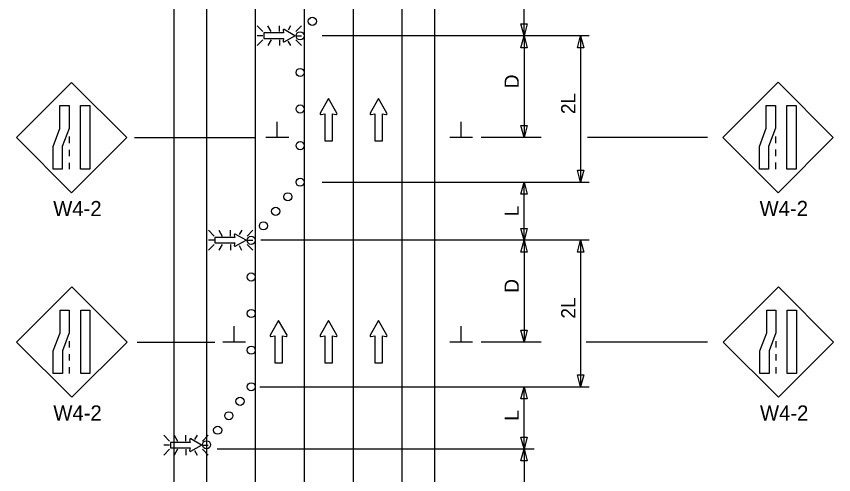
# Model space of a CAD drawing. Extents: x 16364 to 18480, y 5564 to 6927.
# Drawn here: x 16764.6 to 17166.1, y 6445.6 to 6671 of the extents above; entities that cross this region are included whole.
import ezdxf

# ---------------------------------------------------------------- set-up
doc = ezdxf.new("R2010")
doc.units = 0
for name, color, linetype in [('ALI_LEGAL_EX', 7, 'Continuous'), ('MT_SCRATCH_LEVEL_E', 7, 'Continuous'), ('PAVT_EDGE_EX', 7, 'Continuous'), ('TRAFFIC_SIGNS_PR', 7, 'Continuous'), ('TYPICAL_TEXT_DIMEN_PR', 7, 'Continuous')]:
    doc.layers.add(name, color=color, linetype=linetype)

msp = doc.modelspace()

# ---------------------------------------------------------------- linework, layer by layer
at = {"layer": 'ALI_LEGAL_EX'}
for p, q in [((16881.97, 6876.43), (16881.97, 5996.39)), ((16905.97, 6876.43), (16905.97, 5996.39)), ((16929.97, 6876.43), (16929.97, 5996.39))]:
    msp.add_line(p, q, dxfattribs=at)
for points in [[(16881.97, 6596.46), (16881.97, 6571.46)], [(16929.97, 6596.46), (16929.97, 6571.46)], [(16905.97, 6496.46), (16905.97, 6471.46)], [(16929.97, 6496.46), (16929.97, 6471.46)]]:
    msp.add_lwpolyline(points, dxfattribs=at)
at = {"layer": 'MT_SCRATCH_LEVEL_E'}
for p, q in [((16917.93, 6630.62), (16913.82, 6623.38)), ((16922.08, 6623.38), (16917.93, 6630.62)), ((16942.49, 6630.62), (16938.38, 6623.38)), ((16946.64, 6623.38), (16942.49, 6630.62)), ((16914.31, 6622.7), (16916.08, 6623.02)), ((16916.08, 6623.02), (16916.08, 6609.76)), ((16919.82, 6609.76), (16919.82, 6623.02)), ((16919.82, 6623.02), (16921.6, 6622.7)), ((16938.86, 6622.7), (16940.64, 6623.02)), ((16940.64, 6623.02), (16940.64, 6609.76)), ((16944.38, 6609.76), (16944.38, 6623.02)), ((16944.38, 6623.02), (16946.16, 6622.7)), ((16916.08, 6609.76), (16919.82, 6609.76)), ((16940.64, 6609.76), (16944.38, 6609.76)), ((16893.4, 6521.46), (16889.29, 6514.22)), ((16897.55, 6514.22), (16893.4, 6521.46)), ((16917.93, 6521.46), (16913.82, 6514.22)), ((16922.08, 6514.22), (16917.93, 6521.46)), ((16942.49, 6521.46), (16938.38, 6514.22)), ((16946.64, 6514.22), (16942.49, 6521.46)), ((16889.78, 6513.53), (16891.55, 6513.85)), ((16891.55, 6513.85), (16891.55, 6500.59)), ((16895.3, 6500.59), (16895.3, 6513.85)), ((16895.3, 6513.85), (16897.07, 6513.53)), ((16914.31, 6513.53), (16916.08, 6513.85)), ((16916.08, 6513.85), (16916.08, 6500.59)), ((16919.82, 6500.59), (16919.82, 6513.85)), ((16919.82, 6513.85), (16921.6, 6513.53)), ((16938.86, 6513.53), (16940.64, 6513.85)), ((16940.64, 6513.85), (16940.64, 6500.59)), ((16944.38, 6500.59), (16944.38, 6513.85)), ((16944.38, 6513.85), (16946.16, 6513.53)), ((16891.55, 6500.59), (16895.3, 6500.59)), ((16916.08, 6500.59), (16919.82, 6500.59)), ((16940.64, 6500.59), (16944.38, 6500.59))]:
    msp.add_line(p, q, dxfattribs=at)
for centre, start, end in [((16914.23, 6623.16), 150.4248, 279.9638), ((16921.67, 6623.16), 260.0362, 29.7731), ((16938.79, 6623.16), 150.4248, 279.9638), ((16946.23, 6623.16), 260.0362, 29.7731), ((16889.7, 6513.99), 150.4248, 279.9638), ((16897.14, 6513.99), 260.0362, 29.7731), ((16914.23, 6513.99), 150.4248, 279.9638), ((16921.67, 6513.99), 260.0362, 29.7731), ((16938.79, 6513.99), 150.4248, 279.9638), ((16946.23, 6513.99), 260.0362, 29.7731)]:
    msp.add_arc(centre, 0.463, start, end, dxfattribs=at)
at = {"layer": 'PAVT_EDGE_EX'}
for p, q in [((16841.97, 6926.69), (16841.97, 5953.59)), ((16857.97, 6926.69), (16857.97, 5953.59)), ((16953.97, 6926.69), (16953.97, 5953.59)), ((16969.97, 6926.69), (16969.97, 5953.59))]:
    msp.add_line(p, q, dxfattribs=at)
at = {"layer": 'TRAFFIC_SIGNS_PR'}
for p, q in [((16885.74, 6663.52), (16882.92, 6666.34)), ((16888.04, 6666.34), (16889.67, 6663.52)), ((16893.83, 6663.52), (16893.83, 6666.34)), ((16899.3, 6666.34), (16898.09, 6664.25)), ((16904.73, 6666.34), (16901.91, 6663.52)), ((16885.74, 6661.49), (16882.92, 6661.49)), ((16901.91, 6661.49), (16904.73, 6661.49)), ((16885.74, 6659.46), (16882.92, 6656.64)), ((16889.69, 6659.46), (16888.06, 6656.64)), ((16893.83, 6659.46), (16893.83, 6656.64)), ((16898.01, 6658.82), (16899.27, 6656.64)), ((16904.73, 6656.64), (16901.91, 6659.46)), ((16791.75, 6638.5), (16764.6, 6611.35)), ((16818.91, 6611.35), (16791.75, 6638.5)), ((17138.72, 6638.56), (17111.56, 6611.41)), ((17165.87, 6611.41), (17138.72, 6638.56)), ((16764.6, 6611.35), (16791.75, 6584.19)), ((16790.51, 6611.84), (16790.51, 6608.64)), ((16791.75, 6584.19), (16818.91, 6611.35)), ((17111.56, 6611.41), (17138.72, 6584.26)), ((17137.47, 6611.9), (17137.47, 6608.7)), ((17138.72, 6584.26), (17165.87, 6611.41)), ((16790.51, 6605.44), (16790.51, 6602.24)), ((17137.47, 6605.5), (17137.47, 6602.3)), ((16790.51, 6599.04), (16790.51, 6595.84)), ((17137.47, 6599.1), (17137.47, 6595.9)), ((16861.74, 6562.96), (16858.92, 6565.78)), ((16864.04, 6565.78), (16865.67, 6562.96)), ((16869.83, 6562.96), (16869.83, 6565.78)), ((16875.3, 6565.78), (16874.09, 6563.69)), ((16880.73, 6565.78), (16877.91, 6562.96)), ((16861.74, 6560.93), (16858.92, 6560.93)), ((16877.91, 6560.93), (16880.73, 6560.93)), ((16861.74, 6558.89), (16858.92, 6556.07)), ((16865.69, 6558.89), (16864.06, 6556.07)), ((16869.83, 6558.89), (16869.83, 6556.07)), ((16874.01, 6558.26), (16875.27, 6556.07)), ((16880.73, 6556.08), (16877.91, 6558.89)), ((16791.81, 6538), (16764.66, 6510.85)), ((16818.96, 6510.85), (16791.81, 6538)), ((17138.9, 6537.99), (17111.75, 6510.83)), ((17166.05, 6510.83), (17138.9, 6537.99)), ((16764.66, 6510.85), (16791.81, 6483.69)), ((16790.56, 6511.34), (16790.56, 6508.14)), ((16791.81, 6483.69), (16818.96, 6510.85)), ((17111.75, 6510.83), (17138.9, 6483.68)), ((17137.65, 6511.33), (17137.65, 6508.13)), ((17138.9, 6483.68), (17166.05, 6510.83)), ((16790.56, 6504.94), (16790.56, 6501.74)), ((17137.65, 6504.93), (17137.65, 6501.73)), ((16790.56, 6498.54), (16790.56, 6495.34)), ((17137.65, 6498.53), (17137.65, 6495.33)), ((16839.82, 6462.17), (16837, 6464.99)), ((16842.12, 6464.99), (16843.74, 6462.17)), ((16847.9, 6462.17), (16847.9, 6464.99)), ((16853.37, 6464.99), (16852.17, 6462.89)), ((16858.81, 6464.99), (16855.99, 6462.17)), ((16839.82, 6460.14), (16837, 6460.14)), ((16855.99, 6460.14), (16858.81, 6460.14)), ((16839.82, 6458.1), (16837, 6455.28)), ((16843.77, 6458.1), (16842.14, 6455.28)), ((16847.9, 6458.1), (16847.9, 6455.28)), ((16852.09, 6457.47), (16853.35, 6455.28)), ((16858.81, 6455.28), (16855.99, 6458.1))]:
    msp.add_line(p, q, dxfattribs=at)
for points in [[(16895.65, 6664.17), (16895.88, 6662.88), (16886.16, 6662.88), (16886.16, 6660.13), (16895.88, 6660.13), (16895.65, 6658.83)], [(16896.15, 6658.47), (16901.46, 6661.49), (16896.15, 6664.53)], [(16872.15, 6557.91), (16877.46, 6560.93), (16872.15, 6563.97)], [(16871.65, 6563.61), (16871.88, 6562.31), (16862.16, 6562.31), (16862.16, 6559.57), (16871.88, 6559.57), (16871.65, 6558.27)], [(16849.73, 6462.82), (16849.96, 6461.52), (16840.24, 6461.52), (16840.24, 6458.78), (16849.96, 6458.78), (16849.73, 6457.47)], [(16850.23, 6457.12), (16855.54, 6460.14), (16850.23, 6463.18)]]:
    msp.add_lwpolyline(points, dxfattribs=at)
for points in [[(16790.51, 6627.08), (16790.51, 6615.9), (16787.16, 6607.02), (16787.16, 6595.84), (16782.67, 6595.84), (16782.67, 6607.02), (16786.01, 6615.9), (16786.01, 6627.08)], [(16800.64, 6627.08), (16800.64, 6595.84), (16796.15, 6595.84), (16796.15, 6627.08)], [(17137.47, 6627.15), (17137.47, 6615.96), (17134.12, 6607.08), (17134.12, 6595.9), (17129.63, 6595.9), (17129.63, 6607.08), (17132.97, 6615.96), (17132.97, 6627.15)], [(17147.6, 6627.15), (17147.6, 6595.9), (17143.11, 6595.9), (17143.11, 6627.15)], [(16790.56, 6526.58), (16790.56, 6515.4), (16787.22, 6506.52), (16787.22, 6495.34), (16782.72, 6495.34), (16782.72, 6506.52), (16786.07, 6515.4), (16786.07, 6526.58)], [(16800.7, 6526.58), (16800.7, 6495.34), (16796.2, 6495.34), (16796.2, 6526.58)], [(17137.65, 6526.57), (17137.65, 6515.39), (17134.31, 6506.51), (17134.31, 6495.33), (17129.82, 6495.33), (17129.82, 6506.51), (17133.16, 6515.39), (17133.16, 6526.57)], [(17147.79, 6526.57), (17147.79, 6495.33), (17143.3, 6495.33), (17143.3, 6526.57)]]:
    msp.add_lwpolyline(points, close=True, dxfattribs=at)
for centre in [(16909.97, 6668.56), (16903.97, 6661.42), (16903.97, 6643.42), (16903.97, 6625.42), (16903.97, 6607.42), (16903.97, 6589.42), (16897.97, 6582.28), (16891.97, 6575.14), (16885.97, 6568), (16879.97, 6560.86), (16879.97, 6542.86), (16879.97, 6524.86), (16879.97, 6506.86), (16879.97, 6488.86), (16874.47, 6481.72), (16868.97, 6474.6), (16863.47, 6467.47), (16857.98, 6460.34)]:
    msp.add_circle(centre, 2, dxfattribs=at)
for centre, start, end in [((16895.99, 6664.23), 61.4833, 189.9593), ((16895.99, 6658.77), 170.7308, 298.8916), ((16871.99, 6563.67), 61.4833, 189.9593), ((16871.99, 6558.21), 170.7308, 298.8916), ((16850.07, 6462.88), 61.4833, 189.9593), ((16850.07, 6457.42), 170.7308, 298.8916)]:
    msp.add_arc(centre, 0.341, start, end, dxfattribs=at)
at = {"layer": 'TYPICAL_TEXT_DIMEN_PR'}
for p, q in [((17013.97, 6661.42), (17013.97, 6691.98)), ((17013.97, 6661.42), (17012.4, 6667.28)), ((17012.4, 6667.28), (17013.97, 6667.28)), ((17013.97, 6667.28), (17015.54, 6667.28)), ((17015.54, 6667.28), (17013.97, 6661.42)), ((17046.01, 6661.42), (16914.87, 6661.42)), ((17012.4, 6655.56), (17013.97, 6661.42)), ((17013.97, 6661.42), (17013.97, 6611.42)), ((17013.97, 6661.42), (17015.54, 6655.56)), ((17040.2, 6655.56), (17041.77, 6661.42)), ((17041.77, 6661.42), (17043.34, 6655.56)), ((17041.77, 6661.42), (17041.77, 6589.42)), ((17013.97, 6655.56), (17012.4, 6655.56)), ((17015.54, 6655.56), (17013.97, 6655.56)), ((17041.77, 6655.56), (17040.2, 6655.56)), ((17043.34, 6655.56), (17041.77, 6655.56)), ((16892.76, 6611.42), (16892.76, 6619.2)), ((16983.09, 6611.42), (16983.09, 6619.2)), ((17013.97, 6611.42), (17012.4, 6617.28)), ((17012.4, 6617.28), (17013.97, 6617.28)), ((17013.97, 6617.28), (17015.54, 6617.28)), ((17015.54, 6617.28), (17013.97, 6611.42)), ((17041.77, 6616.29), (17041.77, 6612.52)), ((16822.65, 6611.42), (16881.72, 6611.42)), ((16898.39, 6611.42), (16887.14, 6611.42)), ((16988.72, 6611.42), (16977.47, 6611.42)), ((17022.46, 6611.42), (16992.97, 6611.42)), ((17104.13, 6611.42), (17045.17, 6611.42)), ((17041.77, 6589.42), (17040.2, 6595.28)), ((17040.2, 6595.28), (17041.77, 6595.28)), ((17041.77, 6595.28), (17043.34, 6595.28)), ((17043.34, 6595.28), (17041.77, 6589.42)), ((16914.87, 6589.42), (17046.01, 6589.42)), ((17012.4, 6583.56), (17013.97, 6589.42)), ((17013.97, 6560.86), (17013.97, 6589.42)), ((17013.97, 6589.42), (17015.54, 6583.56)), ((17013.97, 6583.56), (17012.4, 6583.56)), ((17015.54, 6583.56), (17013.97, 6583.56)), ((17013.97, 6560.86), (17012.4, 6566.72)), ((17012.4, 6566.72), (17013.97, 6566.72)), ((17013.97, 6566.72), (17015.54, 6566.72)), ((17015.54, 6566.72), (17013.97, 6560.86)), ((17046.01, 6560.86), (16884.68, 6560.86)), ((17012.4, 6554.99), (17013.97, 6560.86)), ((17013.97, 6560.86), (17013.97, 6510.86)), ((17013.97, 6560.86), (17015.54, 6554.99)), ((17040.2, 6554.99), (17041.77, 6560.86)), ((17041.77, 6560.86), (17043.34, 6554.99)), ((17041.77, 6560.86), (17041.77, 6488.86)), ((17013.97, 6554.99), (17012.4, 6554.99)), ((17015.54, 6554.99), (17013.97, 6554.99)), ((17041.77, 6554.99), (17040.2, 6554.99)), ((17043.34, 6554.99), (17041.77, 6554.99)), ((16871.6, 6510.86), (16871.6, 6518.64)), ((16983.09, 6510.86), (16983.09, 6518.64)), ((17013.97, 6510.86), (17012.4, 6516.72)), ((17012.4, 6516.72), (17013.97, 6516.72)), ((17013.97, 6516.72), (17015.54, 6516.72)), ((17015.54, 6516.72), (17013.97, 6510.86)), ((17041.77, 6515.73), (17041.77, 6511.96)), ((16823.89, 6510.86), (16862.16, 6510.86)), ((16877.23, 6510.86), (16865.98, 6510.86)), ((16988.72, 6510.86), (16977.47, 6510.86)), ((17022.46, 6510.86), (16992.97, 6510.86)), ((17104.13, 6510.86), (17044.45, 6510.86)), ((17041.77, 6488.86), (17040.2, 6494.72)), ((17040.2, 6494.72), (17041.77, 6494.72)), ((17041.77, 6494.72), (17043.34, 6494.72)), ((17043.34, 6494.72), (17041.77, 6488.86)), ((16884.15, 6488.86), (17046.01, 6488.86)), ((16914.87, 6488.86), (17046.01, 6488.86)), ((17012.4, 6482.99), (17013.97, 6488.86)), ((17013.97, 6458.29), (17013.97, 6488.86)), ((17013.97, 6488.86), (17015.54, 6482.99)), ((17013.97, 6482.99), (17012.4, 6482.99)), ((17015.54, 6482.99), (17013.97, 6482.99)), ((17013.97, 6458.29), (17012.4, 6464.15)), ((17012.4, 6464.15), (17013.97, 6464.15)), ((17013.97, 6464.15), (17015.54, 6464.15)), ((17015.54, 6464.15), (17013.97, 6458.29)), ((16863.28, 6458.29), (17018.97, 6458.29)), ((17012.4, 6452.43), (17013.97, 6458.29)), ((17013.97, 6458.29), (17013.97, 6408.29)), ((17013.97, 6458.29), (17015.54, 6452.43)), ((17013.97, 6452.43), (17012.4, 6452.43)), ((17015.54, 6452.43), (17013.97, 6452.43))]:
    msp.add_line(p, q, dxfattribs=at)

# ---------------------------------------------------------------- texts
at = {"layer": 'TRAFFIC_SIGNS_PR'}
for p in [(16782.71, 6572.75), (17129.67, 6572.82), (16782.77, 6472.25), (17129.86, 6472.24)]:
    msp.add_text('W4-2', height=7.44, dxfattribs=at).set_placement(p)
at = {"layer": 'TYPICAL_TEXT_DIMEN_PR'}
for s, p in [('D', (17011.41, 6635.64)), ('2L', (17039.21, 6622.92)), ('L', (17011.41, 6572.71)), ('D', (17011.41, 6535.07)), ('2L', (17039.21, 6522.36)), ('L', (17011.41, 6472.15))]:
    msp.add_text(s, height=7, rotation=90, dxfattribs=at).set_placement(p)

doc.saveas('drawing.dxf')
